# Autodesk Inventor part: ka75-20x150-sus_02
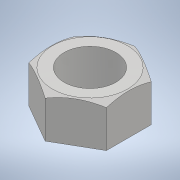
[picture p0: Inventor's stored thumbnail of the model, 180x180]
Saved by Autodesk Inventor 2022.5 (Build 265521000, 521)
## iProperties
Part Number: ka75-20x150-sus_02
Material: 一般
Document SubType Name: Modeling
Designer: ImaoCorp
Density: 1 g/cm^3
Appearance: 既定
Author: ImaoCorp
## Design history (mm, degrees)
feature "ka75-20x150-sus_02"
node "ソリッド1"
